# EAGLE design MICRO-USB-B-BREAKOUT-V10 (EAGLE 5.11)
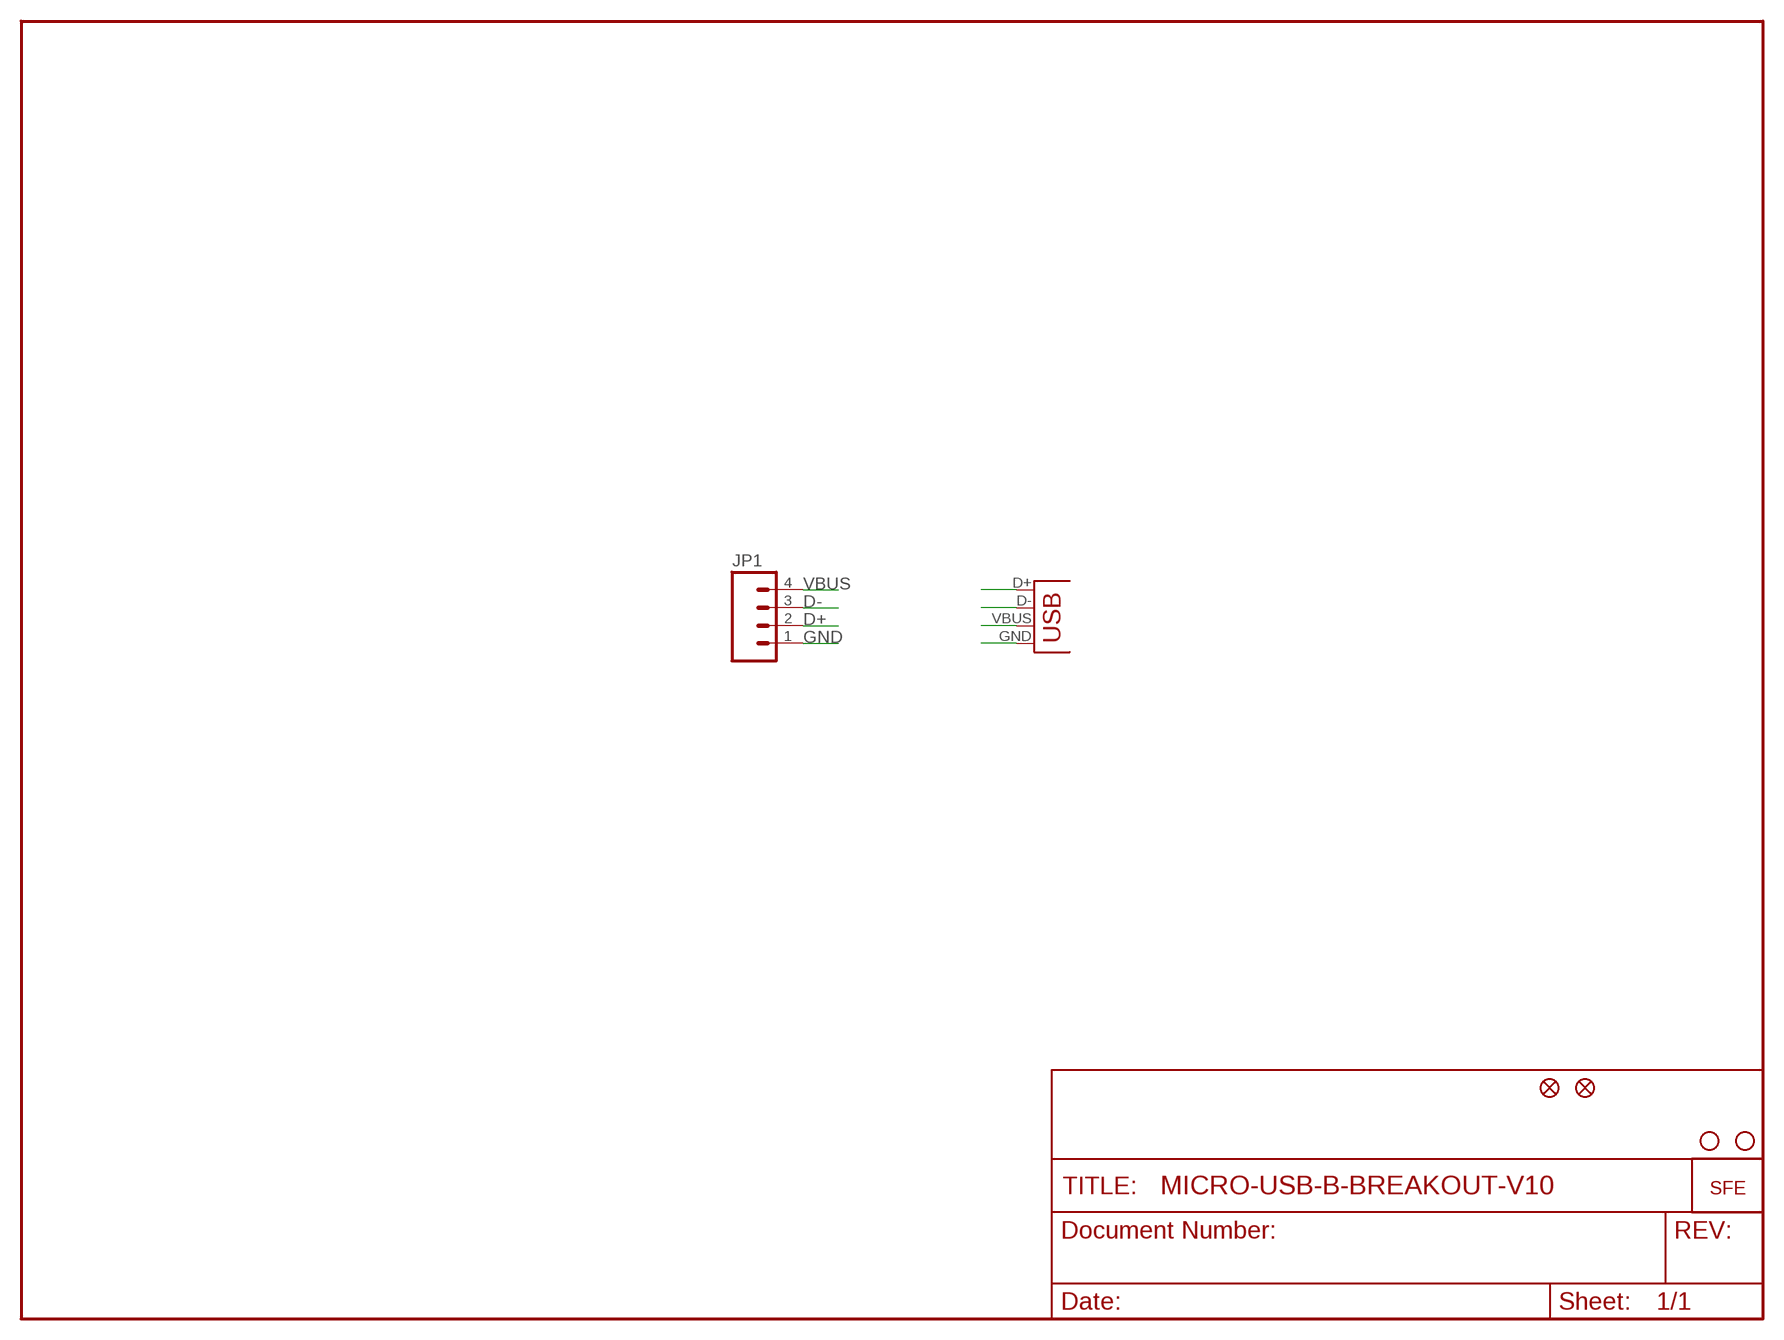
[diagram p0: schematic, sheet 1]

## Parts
JP1  M04PTH  [1X04]
JP2  LOGO-SFESK  [SFE-LOGO-FLAME]
JP3  STAND-OFF  [STAND-OFF]
JP4  STAND-OFF  [STAND-OFF]
JP5  FIDUCIALUFIDUCIAL  [MICRO-FIDUCIAL]
JP6  FIDUCIALUFIDUCIAL  [MICRO-FIDUCIAL]
X1  USB-MICROB  [USB-MICROB]

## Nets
D+: JP1.2 X1.D+
D-: JP1.3 X1.D-
GND: JP1.1 X1.GND
VBUS: JP1.4 X1.VBUS

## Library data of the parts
JP1 = SparkFun:M04: Header 4 Standard 4-pin 0.1" header. Use with straight break away headers (SKU : PRT-00116), right angle break away headers (PRT-00553), swiss pins (PRT-00743), machine pins (PRT-00117), and female headers (PRT-00115). Molex polarized connector foot print use with SKU : PRT-08231 with associated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
JP2 = SparkFun:LOGO-SFE: Spark Fun Electronics PCB Logo
JP3 JP4 = SparkFun:STAND-OFF: Stand Off
JP5 JP6 = SparkFun:FIDUCIAL: Fiducial Alignment Points
X1 = SparkFun:USB: USB Connectors USB-B-PTH is fully proven SKU : PRT-00139 USB-miniB is fully proven SKU : PRT-00587 USB-A-PCB is untested. USB-A-H is throughly reviewed, but untested. Spark Fun Electronics SKU : PRT-00437 USB-B-SMT is throughly reviewed, but untested. Needs silkscreen touching up. USB-A-S has not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

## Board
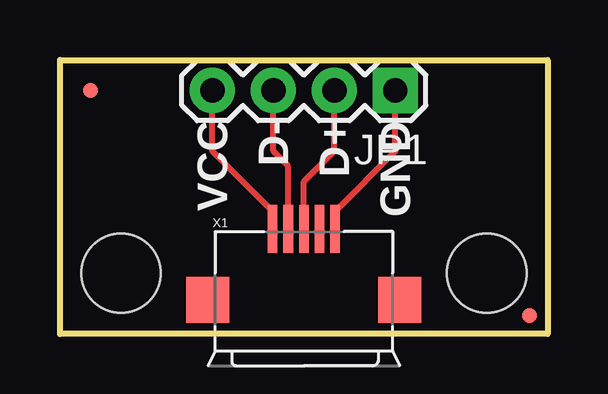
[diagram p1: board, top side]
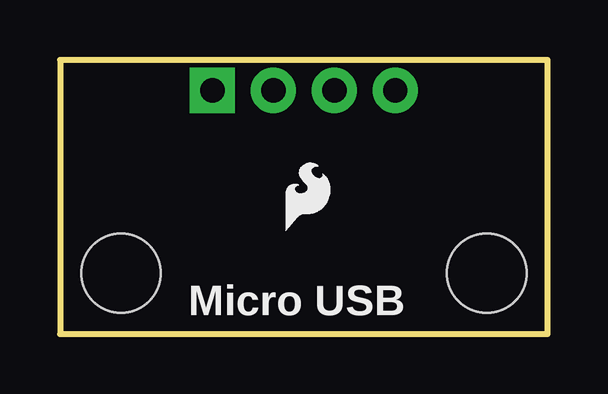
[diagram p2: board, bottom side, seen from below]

Size 20.32 x 11.43 mm. Coordinates in mm from the lower left corner, seen from the top.
Outline: 0,0 0,11.43 20.32,11.43 20.32,0 0,0
Copper layers (1*16): Top 0.035mm / dielectric 1.5mm / Bottom 0.035mm
Design rules "SparkFun": minimum track width 8mil, minimum drill 20mil, track to track 8mil, track to pad 8mil, pad to pad 8mil, via to via 8mil, smd to smd 8mil, copper to edge 9mil, drill to drill 8mil, minimum pad ring 12mil, minimum via ring 10mil, stop-mask expansion 4mil, vias tented up to drill 20mil, thermal gap 10mil

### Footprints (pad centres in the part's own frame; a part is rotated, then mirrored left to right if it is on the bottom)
1X04 = drill 1.016 pad 1.88 square: 1 0,0 | drill 1.016 pad 1.88 round: 2 2.54,0; 3 5.08,0; 4 7.62,0
STAND-OFF = hole 3.302: 0,0
MICRO-FIDUCIAL = smd 0.635 x 0.635: 1 0,0
USB-MICROB = smd 0.4 x 2: D+ 0,3.1; D- -0.65,3.1; GND 1.3,3.1; ID 0.65,3.1; VBUS -1.3,3.1 | smd 1.8 x 1.9: GND@2 -4,0.15; GND@3 4,0.15

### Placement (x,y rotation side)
JP1  13.97,10.16 180 top
JP2  10.92,4.32 0 bottom
JP3  17.78,2.54 0 top
JP4  2.54,2.54 0 top
JP5  1.27,10.16 0 top
JP6  19.56,0.76 0 top
X1  10.16,1.27 0 top

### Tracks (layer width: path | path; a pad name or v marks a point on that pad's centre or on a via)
D+
  Top 0.254: JP1.2 11.43,7.62 10.16,6.35 X1.D+
D-
  Top 0.254: JP1.3 8.89,7.62 9.51,7 X1.D-
GND
  Top 0.254: JP1.1 13.97,7.62 11.46,5.11 X1.GND
VBUS
  Top 0.254: X1.VBUS 8.86,3.84 8.89,3.81 8.89,5.08 6.35,7.62 JP1.4

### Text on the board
tPlace: VCC | D- | D+ | GND
bPlace: Micro USB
